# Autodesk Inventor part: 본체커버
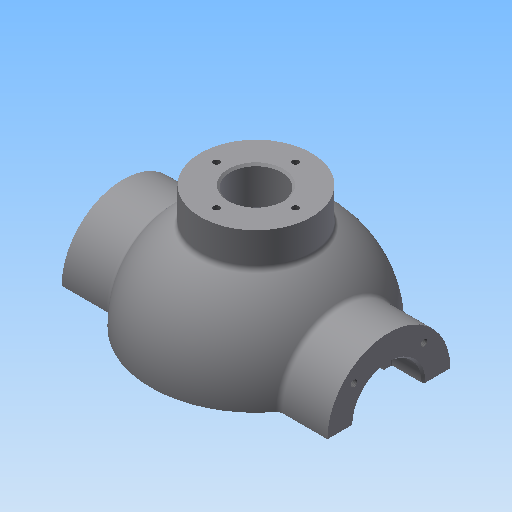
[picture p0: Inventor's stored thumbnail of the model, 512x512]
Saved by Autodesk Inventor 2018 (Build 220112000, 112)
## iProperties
Created: 2015-12
Part Number: 본체커버
Material: 일반
Document SubType Name: Modeling
Designer: mduedu
Density: 1 g/cm^3
Mass: 179.872 g
Surface Area: 431.319 cm^2
Volume: 179.872 cm^3
Appearance: 기본값
Author: mduedu
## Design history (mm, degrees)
sketch "스케치1"
  geometry: L1 (-53, 0)-(53, 0); A1 r 53 centre (0, 0) between (53, 0) and (-53, 0); 2 further points
  constraints: 2 coincident, 2 end point, 2 point on circle, 1 centre point, 1 horizontal, 1 midpoint
  dimensions: "d0" = 53 radius of A1
revolve "회전1" sketch "스케치1" stored, may be unused: angle "d2" = 90 deg
feature "쉘1" dims "d11" = 8
node "작업 평면1"
sketch "스케치2"
  geometry: C1 r 31 at (0, 0); 1 further point
  constraints: 1 centre point, 1 coincident
  dimensions: "d4" = 62 diameter of C1
extrude "돌출1" join sketch "스케치2" stored distance "d5" = 10; taper "d6" = 0 deg
hole "구멍1" diameter "d14" = 35; stored, may be unused: countersink angle "d18" = 90 deg, drill point angle "d20" = 0 deg; dims "d12" = 10, "d13" = 10, "d15" = 6, "d16" = 4, "d17" = 2, "d19" = 16
hole "구멍2" diameter "d23" = 27; stored, may be unused: countersink angle "d27" = 90 deg, drill point angle "d29" = 0 deg; dims "d21" = 10, "d22" = 10, "d24" = 6, "d25" = 4, "d26" = 2, "d28" = 16
fillet "모깎기1" dims "d30" = 0.3
chamfer "모따기1" distance "d40" = 1; stored, may be unused: second distance "d41" = 2, angle "d42" = 45 deg
sketch "스케치4"
  geometry: L1 (0, 0)-(0, -25); L2 (0, 0)-(-17.678, -17.678); A1 r 25 centre (0, 0) between (-17.678, -17.678) and (0, -25); 1 further point
  constraints: 4 end point, 2 point on circle, 1 centre point, 1 coincident, 1 vertical
  dimensions: "d43" = 50 diameter of A1; "d47" = 45 deg angle of L1 L2
hole "구멍4" sketch "스케치4" at (-17.678, -17.678) diameter "d49" = 3.242; stored, may be unused: countersink angle "d53" = 90 deg, drill point angle "d55" = 118 deg; dims "d50" = 11, "d51" = 4, "d52" = 2, "d54" = 13
node "작업 평면3"
sketch "스케치6"
  geometry: C1 r 65 at (0, 0); 1 further point
  constraints: 1 centre point, 1 coincident
  dimensions: "d78" = 130 diameter of C1
extrude "돌출3" join sketch "스케치6" distance "d80" = 10; taper "d81" = 0 deg
sketch "스케치7"
  geometry: C1 r 20 at (0, 0); 1 further point
  constraints: 1 centre point, 1 coincident
  dimensions: "d82" = 40 diameter of C1
extrude "돌출4" join sketch "스케치7" stored distance "d84" = 10; taper "d85" = 0 deg
sketch "스케치8"
  geometry: 2 further points
  constraints: 1 coincident
hole "구멍6" sketch "스케치8" at (0, 0) diameter "d86" = 20; stored, may be unused: countersink angle "d90" = 90 deg, drill point angle "d92" = 118 deg; dims "d87" = 7, "d88" = 40, "d89" = 5, "d91" = 10
fillet "모깎기2" dims "d93" = 0.3
sketch "스케치9"
  geometry: L1 (65, -75)-(-65, -75) reference; L2 (-45, -75)-(-38.245, -36.692); A1 r 53 centre (0, 0) between (42.988, 31) and (42.988, -31) reference; 1 further point
  constraints: 2 end point, 1 point on circle, 1 point on line
  dimensions: "d94" = 45 horizontal distance of L2.start point (0, 0); "d95" = 80 deg angle of L2 L1
feature "리브1" sketch "스케치9" dims "d96" = 1, "d97" = 8, "d98" = 0, "d99" = 0, "d100" = 1, "d101" = 1
sketch "스케치10"
  geometry: L1 (0, 0)-(0, -55); L2 (0, 0)-(-38.891, -38.891); A1 r 55 centre (0, 0) between (0, -55) and (-38.891, -38.891); 2 further points
  constraints: 4 end point, 2 coincident, 2 point on circle, 1 centre point, 1 vertical
  dimensions: "d105" = 110 diameter of A1; "d107" = 45 deg angle of L1 L2
hole "구멍7" sketch "스케치10" at (-38.891, -38.891) diameter "d109" = 10; stored, may be unused: countersink angle "d113" = 90 deg, drill point angle "d115" = 118 deg; dims "d110" = 7, "d111" = 40, "d112" = 5, "d114" = 10
fillet "모깎기3" dims "d120" = 3
fillet "모깎기4" dims "d121" = 3, "d122" = 3
fillet "모깎기5" dims "d123" = 3
fillet "모깎기6" dims "d124" = 3
sketch "스케치11"
  geometry: C1 r 5 at (-38.891, 38.891) reference; C2 r 5 at (38.891, 38.891) reference; C3 r 5 at (38.891, -38.891) reference; C4 r 5 at (-38.891, -38.891) reference; C5 r 20 at (0, 0) reference; C6 r 65 at (0, 0) reference; 1 further point
  constraints: 3 other
feature "엠보싱1" sketch "스케치11" dims "d125" = 0.5, "d126" = 0
sketch "스케치12"
  geometry: L1 (0, 100)-(0, -100); L2 (0, 100)-(-150, 100); L3 (-150, 100)-(-150, -100); L4 (-150, -100)-(0, -100); 2 further points
  constraints: 8 end point, 3 perpendicular, 1 coincident, 1 midpoint, 1 vertical
  dimensions: "d127" = 200 distance of L2.end L3.end; "d129" = 150 distance of L3.end L1.end
extrude "돌출5" cut sketch "스케치12" extent not by distance; stored distance "d130" = 10; taper "d131" = 0 deg
node "작업 평면4"
sketch "스케치16"
  geometry: C1 r 28 at (0, 0); 1 further point
  constraints: 1 centre point, 1 coincident
  dimensions: "d148" = 56 diameter of C1
extrude "돌출9" join sketch "스케치16" stored distance "d150" = 5; taper "d151" = 0 deg
hole "구멍8" diameter "d154" = 26; stored, may be unused: countersink angle "d158" = 90 deg, drill point angle "d160" = 118 deg; dims "d152" = 10, "d153" = 10, "d155" = 6, "d156" = 4, "d157" = 2, "d159" = 8
sketch "스케치17" dims "d161" = 40
  geometry: 3 further points
  constraints: 2 vertical alignment, 1 coincident, 2 other
hole "구멍9" sketch "스케치17" at (0, 20) diameter "d163" = 3.242; stored, may be unused: countersink angle "d167" = 90 deg, drill point angle "d169" = 118 deg; dims "d164" = 8, "d165" = 4, "d166" = 2, "d168" = 10
fillet "모깎기11" dims "d173" = 3
chamfer "모따기2" distance "d174" = 1; stored, may be unused: second distance "d175" = 2, angle "d176" = 45 deg
node "솔리드1"
mirror "대칭1"
mirror "대칭2"
pattern_circular "원형 패턴1" dims angle "d57" = 360 deg
mirror "대칭3"
pattern_circular "원형 패턴3" dims angle "d103" = 360 deg
pattern_circular "원형 패턴4" dims angle "d118" = 360 deg
pattern_circular "원형 패턴5" dims angle "d171" = 360 deg
node "투영된 루프1"
other parameters: "d3" = 67, "d77" = -85, "d147" = 62
